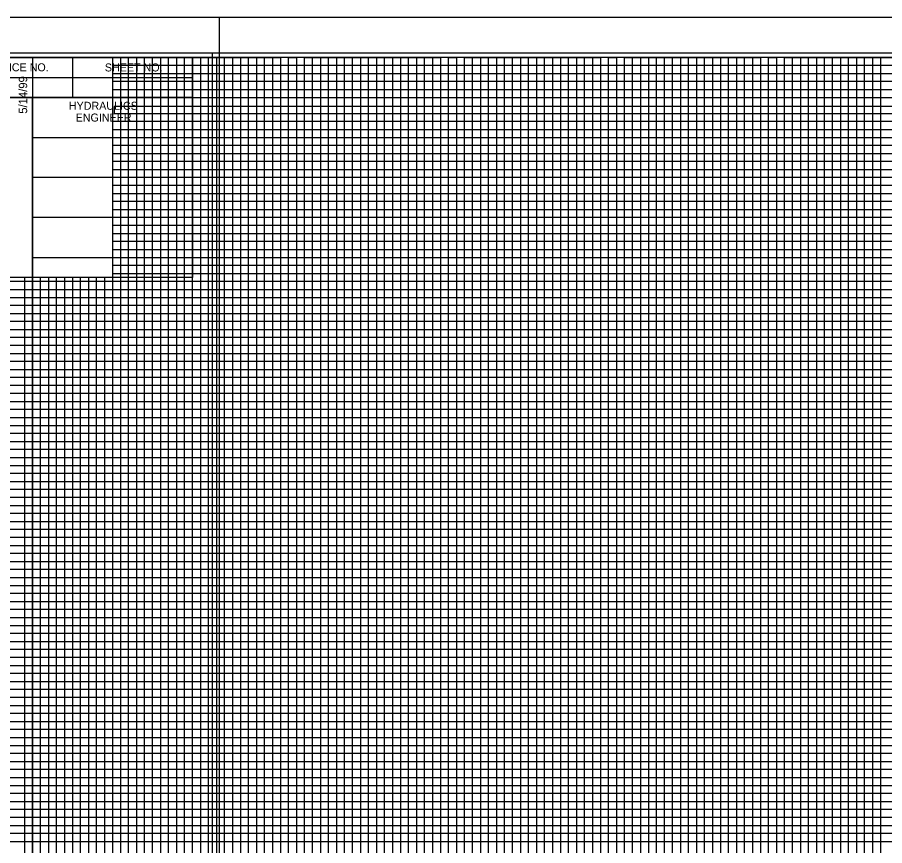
# Model space of a CAD drawing. Extents: x 2345490 to 2436403, y 465165 to 573888.
# Drawn here: x 2384421 to 2384963, y 536733 to 537251 of the extents above; entities that cross this region are included whole.
import ezdxf

# ---------------------------------------------------------------- set-up
doc = ezdxf.new("R2010")
doc.units = 0
for name, color, linetype in [('Old_Level_1', 7, 'Continuous'), ('Old_Level_18', 7, 'Continuous'), ('Old_Level_40', 7, 'Continuous'), ('Old_Level_41', 7, 'Continuous'), ('Old_Level_42', 7, 'Continuous'), ('Old_Level_43', 7, 'Continuous'), ('Old_Level_44', 7, 'Continuous'), ('Old_Level_50', 7, 'Continuous'), ('Old_Level_51', 7, 'Continuous'), ('Old_Level_52', 7, 'Continuous'), ('Old_Level_53', 7, 'Continuous')]:
    doc.layers.add(name, color=color, linetype=linetype)

msp = doc.modelspace()

# ---------------------------------------------------------------- linework, layer by layer
at = {"layer": 'Old_Level_1'}
msp.add_line((2384542.954, 537228.23175), (2384542.954, 537228.23175), dxfattribs=at)
at = {"layer": 'Old_Level_18'}
for points in [[(2384530.454, 537225.68175), (2383030.454, 537225.68175), (2383030.454, 536175.68175), (2384530.454, 536175.68175)], [(2385930.454, 537225.68175), (2384430.454, 537225.68175), (2384430.454, 536175.68175), (2385930.454, 536175.68175)]]:
    msp.add_lwpolyline(points, close=True, dxfattribs=at)
at = {"layer": 'Old_Level_40'}
for p, q in [((2384455.454, 537225.63175), (2384455.454, 537200.63175)), ((2384330.404, 537213.13175), (2384530.454, 537213.13175)), ((2384430.454, 537200.63175), (2384430.454, 537088.18175))]:
    msp.add_line(p, q, dxfattribs=at)
for points in [[(2384330.404, 537225.68175), (2384530.454, 537225.68175), (2384530.454, 537200.63175), (2384330.404, 537200.63175)], [(2384330.404, 537200.63175), (2384430.454, 537200.63175), (2384430.454, 537088.13175), (2384330.404, 537088.13175)], [(2384430.454, 537200.63175), (2384530.454, 537200.63175), (2384530.454, 537088.13175), (2384430.454, 537088.13175)]]:
    msp.add_lwpolyline(points, close=True, dxfattribs=at)
at = {"layer": 'Old_Level_41'}
for points in [[(2384430.454, 537225.68175), (2384480.454, 537225.68175), (2384480.454, 536200.68175), (2384530.454, 536200.68175), (2384530.454, 537225.68175), (2384580.454, 537225.68175), (2384580.454, 536200.68175), (2384630.454, 536200.68175), (2384630.454, 537225.68175), (2384680.454, 537225.68175), (2384680.454, 536200.68175), (2384730.454, 536200.68175), (2384730.454, 537225.68175), (2384780.454, 537225.68175), (2384780.454, 536200.68175), (2384830.454, 536200.68175), (2384830.454, 537225.68175), (2384880.454, 537225.68175), (2384880.454, 536200.68175), (2384930.454, 536200.68175), (2384930.454, 537225.68175), (2384980.454, 537225.68175)], [(2384505.454, 536200.68175), (2384505.454, 537225.68175), (2384555.454, 537225.68175), (2384555.454, 536200.68175), (2384605.454, 536200.68175), (2384605.454, 537225.68175), (2384655.454, 537225.68175), (2384655.454, 536200.68175), (2384705.454, 536200.68175), (2384705.454, 537225.68175), (2384755.454, 537225.68175), (2384755.454, 536200.68175), (2384805.454, 536200.68175), (2384805.454, 537225.68175), (2384855.454, 537225.68175), (2384855.454, 536200.68175), (2384905.454, 536200.68175), (2384905.454, 537225.68175), (2384955.454, 537225.68175), (2384955.454, 536200.68175), (2385005.454, 536200.68175)], [(2384430.454, 537175.68175), (2385730.404, 537175.68175)], [(2384330.404, 537125.68175), (2383030.454, 537125.68175), (2383030.454, 537075.63175), (2384530.454, 537075.63175)], [(2385730.404, 537125.68175), (2384430.454, 537125.68175), (2384430.454, 537075.63175), (2385930.454, 537075.63175)], [(2384530.454, 537050.68175), (2383030.454, 537050.68175), (2383030.454, 537100.68175), (2384330.404, 537100.68175)], [(2385930.454, 537050.68175), (2384430.454, 537050.68175), (2384430.454, 537100.68175), (2385730.404, 537100.68175)], [(2384455.454, 537088.13175), (2384455.454, 536200.68175)], [(2384530.454, 537025.68175), (2383030.454, 537025.68175), (2383030.454, 536975.68175), (2384530.454, 536975.68175)], [(2385930.454, 537025.68175), (2384430.454, 537025.68175), (2384430.454, 536975.68175), (2385930.454, 536975.68175)], [(2384530.454, 536950.68175), (2383030.454, 536950.68175), (2383030.454, 537000.68175), (2384530.454, 537000.68175)], [(2385930.454, 536950.68175), (2384430.454, 536950.68175), (2384430.454, 537000.68175), (2385930.454, 537000.68175)], [(2384530.454, 536925.68175), (2383030.454, 536925.68175), (2383030.454, 536875.68175), (2384530.454, 536875.68175)], [(2385930.454, 536925.68175), (2384430.454, 536925.68175), (2384430.454, 536875.68175), (2385930.454, 536875.68175)], [(2384530.454, 536825.68175), (2383030.454, 536825.68175), (2383030.454, 536775.68175), (2384530.454, 536775.68175)], [(2385930.454, 536825.68175), (2384430.454, 536825.68175), (2384430.454, 536775.68175), (2385930.454, 536775.68175)]]:
    msp.add_lwpolyline(points, dxfattribs=at)
at = {"layer": 'Old_Level_42'}
for points in [[(2385730.404, 537150.68175), (2384430.554, 537150.68175), (2384430.554, 537200.63175), (2385730.404, 537200.63175)], [(2384380.454, 537088.13175), (2384380.454, 536200.68175), (2384430.454, 536200.68175), (2384430.454, 537088.13175)], [(2384480.454, 537088.13175), (2384480.454, 536200.68175), (2384530.454, 536200.68175)], [(2384530.454, 536850.68175), (2383030.454, 536850.68175), (2383030.454, 536900.68175), (2384530.454, 536900.68175)], [(2385930.454, 536850.68175), (2384430.454, 536850.68175), (2384430.454, 536900.68175), (2385930.454, 536900.68175)], [(2384530.454, 536750.68175), (2383030.454, 536750.68175), (2383030.454, 536800.68175), (2384530.454, 536800.68175)], [(2385930.454, 536750.68175), (2384430.454, 536750.68175), (2384430.454, 536800.68175), (2385930.454, 536800.68175)]]:
    msp.add_lwpolyline(points, dxfattribs=at)
at = {"layer": 'Old_Level_43'}
for p, q in [((2384480.454, 537045.68175), (2383080.454, 537045.68175)), ((2385880.454, 537045.68175), (2384480.454, 537045.68175)), ((2384480.454, 537045.68175), (2384480.454, 537040.68175)), ((2383080.454, 537040.68175), (2384480.454, 537040.68175)), ((2384480.454, 537040.68175), (2385880.454, 537040.68175)), ((2384480.454, 537020.68175), (2383080.454, 537020.68175)), ((2385880.454, 537020.68175), (2384480.454, 537020.68175))]:
    msp.add_line(p, q, dxfattribs=at)
for points in [[(2384485.454, 537225.68175), (2384490.454, 537225.68175), (2384495.454, 537225.68175), (2384500.454, 537225.68175), (2384510.454, 537225.68175), (2384477.404, 537225.68175), (2384482.404, 537225.68175), (2384440.454, 537225.68175), (2384445.454, 537225.68175), (2384450.454, 537225.68175), (2384460.454, 537225.68175), (2384465.454, 537225.68175), (2384470.454, 537225.68175), (2384475.454, 537225.68175), (2384485.454, 537225.68175), (2384485.454, 536200.68175)], [(2384490.454, 536200.68175), (2384490.454, 537225.68175), (2384495.454, 537225.68175), (2384495.454, 536200.68175)], [(2384500.454, 536200.68175), (2384500.454, 537225.68175), (2384510.454, 537225.68175), (2384510.454, 536200.68175)], [(2384515.454, 536200.68175), (2384515.454, 537225.68175), (2384520.454, 537225.68175), (2384520.454, 536200.68175)], [(2384525.454, 536200.68175), (2384525.454, 537225.68175), (2384535.454, 537225.68175), (2384535.454, 536200.68175)], [(2384540.454, 536200.68175), (2384540.454, 537225.68175), (2384545.454, 537225.68175), (2384545.454, 536200.68175)], [(2384550.454, 536200.68175), (2384550.454, 537225.68175), (2384560.454, 537225.68175), (2384560.454, 536200.68175)], [(2384565.454, 536200.68175), (2384565.454, 537225.68175), (2384570.454, 537225.68175), (2384570.454, 536200.68175)], [(2384575.454, 536200.68175), (2384575.454, 537225.68175), (2384585.454, 537225.68175), (2384585.454, 536200.68175)], [(2384590.454, 536200.68175), (2384590.454, 537225.68175), (2384595.454, 537225.68175), (2384595.454, 536200.68175)], [(2384600.454, 536200.68175), (2384600.454, 537225.68175), (2384610.454, 537225.68175), (2384610.454, 536200.68175)], [(2384615.454, 536200.68175), (2384615.454, 537225.68175), (2384620.454, 537225.68175), (2384620.454, 536200.68175)], [(2384625.454, 536200.68175), (2384625.454, 537225.68175), (2384635.454, 537225.68175), (2384635.454, 536200.68175)], [(2384640.454, 536200.68175), (2384640.454, 537225.68175), (2384645.454, 537225.68175), (2384645.454, 536200.68175)], [(2384650.454, 536200.68175), (2384650.454, 537225.68175), (2384660.454, 537225.68175), (2384660.454, 536200.68175)], [(2384665.454, 536200.68175), (2384665.454, 537225.68175), (2384670.454, 537225.68175), (2384670.454, 536200.68175)], [(2384675.454, 536200.68175), (2384675.454, 537225.68175), (2384685.454, 537225.68175), (2384685.454, 536200.68175)], [(2384690.454, 536200.68175), (2384690.454, 537225.68175), (2384690.454, 537225.68175), (2384695.454, 537225.68175), (2384695.454, 536200.68175)], [(2384700.454, 536200.68175), (2384700.454, 537225.68175), (2384710.454, 537225.68175), (2384710.454, 536200.68175)], [(2384715.454, 536200.68175), (2384715.454, 537225.68175), (2384720.454, 537225.68175), (2384720.454, 536200.68175)], [(2384725.454, 536200.68175), (2384725.454, 537225.68175), (2384735.454, 537225.68175), (2384735.454, 536200.68175)], [(2384740.454, 536200.68175), (2384740.454, 537225.68175), (2384745.454, 537225.68175), (2384745.454, 536200.68175)], [(2384750.454, 536200.68175), (2384750.454, 537225.68175), (2384760.454, 537225.68175), (2384760.454, 536200.68175)], [(2384765.454, 536200.68175), (2384765.454, 537225.68175), (2384770.454, 537225.68175), (2384770.454, 536200.68175)], [(2384775.454, 536200.68175), (2384775.454, 537225.68175), (2384785.454, 537225.68175), (2384785.454, 536200.68175)], [(2384790.454, 536200.68175), (2384790.454, 537225.68175), (2384795.454, 537225.68175), (2384795.454, 536200.68175)], [(2384800.454, 536200.68175), (2384800.454, 537225.68175), (2384810.454, 537225.68175), (2384810.454, 536200.68175)], [(2384815.454, 537225.68175), (2384815.454, 536200.68175), (2384820.454, 536200.68175), (2384820.454, 537225.68175)], [(2384815.454, 537225.08175), (2384815.454, 536200.68175), (2384820.454, 536200.68175), (2384820.454, 537225.08175)], [(2384825.454, 536200.68175), (2384825.454, 537225.68175), (2384835.454, 537225.68175), (2384835.454, 536200.68175)], [(2384840.454, 536200.68175), (2384840.454, 537225.68175), (2384845.454, 537225.68175), (2384845.454, 536200.68175)], [(2384850.454, 536200.68175), (2384850.454, 537225.68175), (2384860.454, 537225.68175), (2384860.454, 536200.68175)], [(2384865.454, 536200.68175), (2384865.454, 537225.68175), (2384870.454, 537225.68175), (2384870.454, 536200.68175)], [(2384875.454, 536200.68175), (2384875.454, 537225.68175), (2384885.454, 537225.68175), (2384885.454, 536200.68175)], [(2384890.454, 536200.68175), (2384890.454, 537225.68175), (2384895.454, 537225.68175), (2384895.454, 536200.68175)], [(2384900.454, 536200.68175), (2384900.454, 537225.68175), (2384910.454, 537225.68175), (2384910.454, 536200.68175)], [(2384915.454, 536200.68175), (2384915.454, 537225.68175), (2384920.454, 537225.68175), (2384920.454, 536200.68175)], [(2384925.454, 536200.68175), (2384925.454, 537225.68175), (2384935.454, 537225.68175), (2384935.454, 536200.68175)], [(2384940.454, 536200.68175), (2384940.454, 537225.68175), (2384945.454, 537225.68175), (2384945.454, 536200.68175)], [(2384950.454, 536200.68175), (2384950.454, 537225.68175), (2384960.454, 537225.68175), (2384960.454, 536200.68175)], [(2385730.404, 537220.68175), (2384480.454, 537220.68175), (2384480.454, 537215.68175), (2385730.404, 537215.68175)], [(2385730.404, 537210.68175), (2384480.454, 537210.68175), (2384480.454, 537205.68175), (2385730.404, 537205.68175)], [(2385730.404, 537194.93175), (2384481.454, 537194.93175), (2384481.454, 537190.68175), (2385730.404, 537190.68175)], [(2385730.404, 537185.68175), (2384480.454, 537185.68175), (2384480.454, 537180.68175), (2385730.404, 537180.68175)], [(2385730.404, 537170.68175), (2384480.454, 537170.68175), (2384480.454, 537165.68175), (2385730.404, 537165.68175)], [(2385730.404, 537160.68175), (2384480.454, 537160.68175), (2384480.454, 537155.68175), (2385730.404, 537155.68175)], [(2385730.404, 537145.68175), (2384480.454, 537145.68175), (2384480.454, 537140.68175), (2385730.404, 537140.68175)], [(2385730.404, 537135.68175), (2384480.454, 537135.68175), (2384480.454, 537130.68175), (2385730.404, 537130.68175)], [(2385730.404, 537120.68175), (2384480.454, 537120.68175), (2384480.454, 537115.68175), (2385730.404, 537115.68175)], [(2385730.404, 537110.68175), (2384480.454, 537110.68175), (2384480.454, 537105.68175), (2385730.404, 537105.68175)], [(2385730.404, 537095.68175), (2384480.454, 537095.68175), (2384480.454, 537090.68175), (2385730.404, 537090.68175)], [(2384480.454, 537085.68175), (2383080.454, 537085.68175), (2383080.454, 537085.68175), (2383080.454, 537065.68175), (2384480.454, 537065.68175)], [(2384425.454, 537088.13175), (2384425.454, 536200.68175), (2384435.454, 536200.68175), (2384435.454, 537088.13175)], [(2384440.454, 537088.13175), (2384440.454, 536200.68175), (2384445.454, 536200.68175), (2384445.454, 537088.13175)], [(2384450.454, 537088.13175), (2384450.454, 536200.68175), (2384460.454, 536200.68175), (2384460.454, 537088.13175)], [(2384465.454, 537088.13175), (2384465.454, 536200.68175), (2384470.454, 536200.68175), (2384470.454, 537088.13175)], [(2384475.454, 537088.13175), (2384475.454, 536200.68175), (2384485.454, 536200.68175)], [(2385880.454, 537085.68175), (2384480.454, 537085.68175), (2384480.454, 537085.68175), (2384480.454, 537065.68175), (2385880.454, 537065.68175)], [(2383080.454, 537080.68175), (2384480.454, 537080.68175)], [(2384480.454, 537080.68175), (2385880.454, 537080.68175)], [(2384480.454, 537070.68175), (2383080.454, 537070.68175)], [(2385880.454, 537070.68175), (2384480.454, 537070.68175)], [(2384480.454, 537060.68175), (2383080.454, 537060.68175), (2383080.454, 537055.68175), (2384480.454, 537055.68175)], [(2385880.454, 537060.68175), (2384480.454, 537060.68175), (2384480.454, 537055.68175), (2385880.454, 537055.68175)], [(2384480.454, 537035.68175), (2383080.454, 537035.68175), (2383080.454, 537030.68175), (2384480.454, 537030.68175)], [(2385880.454, 537035.68175), (2384480.454, 537035.68175), (2384480.454, 537030.68175), (2385880.454, 537030.68175)], [(2384480.454, 537015.68175), (2383080.454, 537015.68175), (2383080.454, 537010.68175), (2384480.454, 537010.68175)], [(2385880.454, 537015.68175), (2384480.454, 537015.68175), (2384480.454, 537010.68175), (2385880.454, 537010.68175)], [(2384480.454, 537005.68175), (2383080.454, 537005.68175)], [(2385880.454, 537005.68175), (2384480.454, 537005.68175)], [(2383080.454, 536995.68175), (2384480.454, 536995.68175)], [(2384480.454, 536995.68175), (2385880.454, 536995.68175)], [(2384480.454, 536990.68175), (2383080.454, 536990.68175), (2383080.454, 536985.68175), (2384480.454, 536985.68175)], [(2385880.454, 536990.68175), (2384480.454, 536990.68175), (2384480.454, 536985.68175), (2385880.454, 536985.68175)], [(2384480.454, 536980.68175), (2383080.454, 536980.68175), (2383080.454, 536970.68175), (2384480.454, 536970.68175)], [(2385880.454, 536980.68175), (2384480.454, 536980.68175), (2384480.454, 536970.68175), (2385880.454, 536970.68175)], [(2384480.454, 536965.68175), (2383080.454, 536965.68175), (2383080.454, 536960.68175), (2384480.454, 536960.68175)], [(2385880.454, 536965.68175), (2384480.454, 536965.68175), (2384480.454, 536960.68175), (2385880.454, 536960.68175)], [(2384480.454, 536955.68175), (2383080.454, 536955.68175), (2383080.454, 536945.68175), (2384480.454, 536945.68175)], [(2385880.454, 536955.68175), (2384480.454, 536955.68175), (2384480.454, 536945.68175), (2385880.454, 536945.68175)], [(2384480.454, 536940.68175), (2383080.454, 536940.68175), (2383080.454, 536935.68175), (2384480.454, 536935.68175)], [(2385880.454, 536940.68175), (2384480.454, 536940.68175), (2384480.454, 536935.68175), (2385880.454, 536935.68175)], [(2384480.454, 536930.68175), (2383080.454, 536930.68175), (2383080.454, 536920.68175), (2384480.454, 536920.68175)], [(2385880.454, 536930.68175), (2384480.454, 536930.68175), (2384480.454, 536920.68175), (2385880.454, 536920.68175)], [(2384480.454, 536915.68175), (2383080.454, 536915.68175), (2383080.454, 536910.68175), (2384480.454, 536910.68175)], [(2385880.454, 536915.68175), (2384480.454, 536915.68175), (2384480.454, 536910.68175), (2385880.454, 536910.68175)], [(2384480.454, 536905.68175), (2383080.454, 536905.68175), (2383080.454, 536895.68175), (2384480.454, 536895.68175)], [(2385880.454, 536905.68175), (2384480.454, 536905.68175), (2384480.454, 536895.68175), (2385880.454, 536895.68175)], [(2384480.454, 536890.68175), (2383080.454, 536890.68175), (2383080.454, 536885.68175), (2384480.454, 536885.68175)], [(2385880.454, 536890.68175), (2384480.454, 536890.68175), (2384480.454, 536885.68175), (2385880.454, 536885.68175)], [(2384480.454, 536880.68175), (2383080.454, 536880.68175), (2383080.454, 536870.68175), (2384480.454, 536870.68175)], [(2385880.454, 536880.68175), (2384480.454, 536880.68175), (2384480.454, 536870.68175), (2385880.454, 536870.68175)], [(2384480.454, 536865.68175), (2383080.454, 536865.68175), (2383080.454, 536860.68175), (2384480.454, 536860.68175)], [(2385880.454, 536865.68175), (2384480.454, 536865.68175), (2384480.454, 536860.68175), (2385880.454, 536860.68175)], [(2384480.454, 536855.68175), (2383080.454, 536855.68175), (2383080.454, 536845.68175), (2384480.454, 536845.68175)], [(2385880.454, 536855.68175), (2384480.454, 536855.68175), (2384480.454, 536845.68175), (2385880.454, 536845.68175)], [(2384480.454, 536840.68175), (2383080.454, 536840.68175), (2383080.454, 536835.68175), (2384480.454, 536835.68175)], [(2385880.454, 536840.68175), (2384480.454, 536840.68175), (2384480.454, 536835.68175), (2385880.454, 536835.68175)], [(2384480.454, 536830.68175), (2383080.454, 536830.68175), (2383080.454, 536820.68175), (2384480.454, 536820.68175)], [(2385880.454, 536830.68175), (2384480.454, 536830.68175), (2384480.454, 536820.68175), (2385880.454, 536820.68175)], [(2384480.454, 536815.68175), (2383080.454, 536815.68175), (2383080.454, 536810.68175), (2384480.454, 536810.68175)], [(2385880.454, 536815.68175), (2384480.454, 536815.68175), (2384480.454, 536810.68175), (2385880.454, 536810.68175)], [(2384480.454, 536805.68175), (2383080.454, 536805.68175), (2383080.454, 536795.68175), (2384480.454, 536795.68175)], [(2385880.454, 536805.68175), (2384480.454, 536805.68175), (2384480.454, 536795.68175), (2385880.454, 536795.68175)], [(2384480.454, 536790.68175), (2383080.454, 536790.68175), (2383080.454, 536785.68175), (2384480.454, 536785.68175)], [(2385880.454, 536790.68175), (2384480.454, 536790.68175), (2384480.454, 536785.68175), (2385880.454, 536785.68175)], [(2384480.454, 536780.68175), (2383080.454, 536780.68175), (2383080.454, 536770.68175), (2384480.454, 536770.68175)], [(2385880.454, 536780.68175), (2384480.454, 536780.68175), (2384480.454, 536770.68175), (2385880.454, 536770.68175)], [(2384480.454, 536765.68175), (2383080.454, 536765.68175), (2383080.454, 536760.68175), (2384480.454, 536760.68175)], [(2385880.454, 536765.68175), (2384480.454, 536765.68175), (2384480.454, 536760.68175), (2385880.454, 536760.68175)], [(2384480.454, 536755.68175), (2383080.454, 536755.68175), (2383080.454, 536745.68175), (2384480.454, 536745.68175)], [(2385880.454, 536755.68175), (2384480.454, 536755.68175), (2384480.454, 536745.68175), (2385880.454, 536745.68175)], [(2384480.454, 536740.68175), (2383080.454, 536740.68175), (2383080.454, 536735.68175), (2384480.454, 536735.68175)], [(2385880.454, 536740.68175), (2384480.454, 536740.68175), (2384480.454, 536735.68175), (2385880.454, 536735.68175)]]:
    msp.add_lwpolyline(points, dxfattribs=at)
at = {"layer": 'Old_Level_50'}
msp.add_line((2384547.454, 537250.68175), (2384547.454, 537250.68175), dxfattribs=at)
for points in [[(2384542.954, 537228.23175), (2382876.454, 537228.23175), (2382876.454, 536173.13175), (2384542.954, 536173.13175)], [(2385942.954, 537228.23175), (2384276.454, 537228.23175), (2384276.454, 536173.13175), (2385942.954, 536173.13175)]]:
    msp.add_lwpolyline(points, close=True, dxfattribs=at)
at = {"layer": 'Old_Level_51'}
for points in [[(2384547.454, 537250.68175), (2382863.454, 537250.68175), (2382863.454, 536150.68175), (2384547.454, 536150.68175)], [(2385947.454, 537250.68175), (2384263.454, 537250.68175), (2384263.454, 536150.68175), (2385947.454, 536150.68175)]]:
    msp.add_lwpolyline(points, close=True, dxfattribs=at)
at = {"layer": 'Old_Level_52'}
msp.add_line((2384542.954, 537228.23175), (2384542.954, 537228.23175), dxfattribs=at)
at = {"layer": 'Old_Level_53'}
msp.add_line((2384542.954, 537228.23175), (2384542.954, 537228.23175), dxfattribs=at)

# ---------------------------------------------------------------- texts
at = {"layer": 'Old_Level_41'}
msp.add_text('5/14/99', height=5.25, rotation=90, dxfattribs=at).set_placement((2384427.204, 537190.48175))
at = {"layer": 'Old_Level_44'}
for s, p in [('PROJECT REFERENCE NO.', (2384352.604, 537216.98175)), ('SHEET NO.', (2384475.754, 537216.88175)), ('HYDRAULICS', (2384453.254, 537192.93175)), ('ENGINEER', (2384457.504, 537185.58175))]:
    msp.add_text(s, height=5.0001, dxfattribs=at).set_placement(p)

doc.saveas('drawing.dxf')
